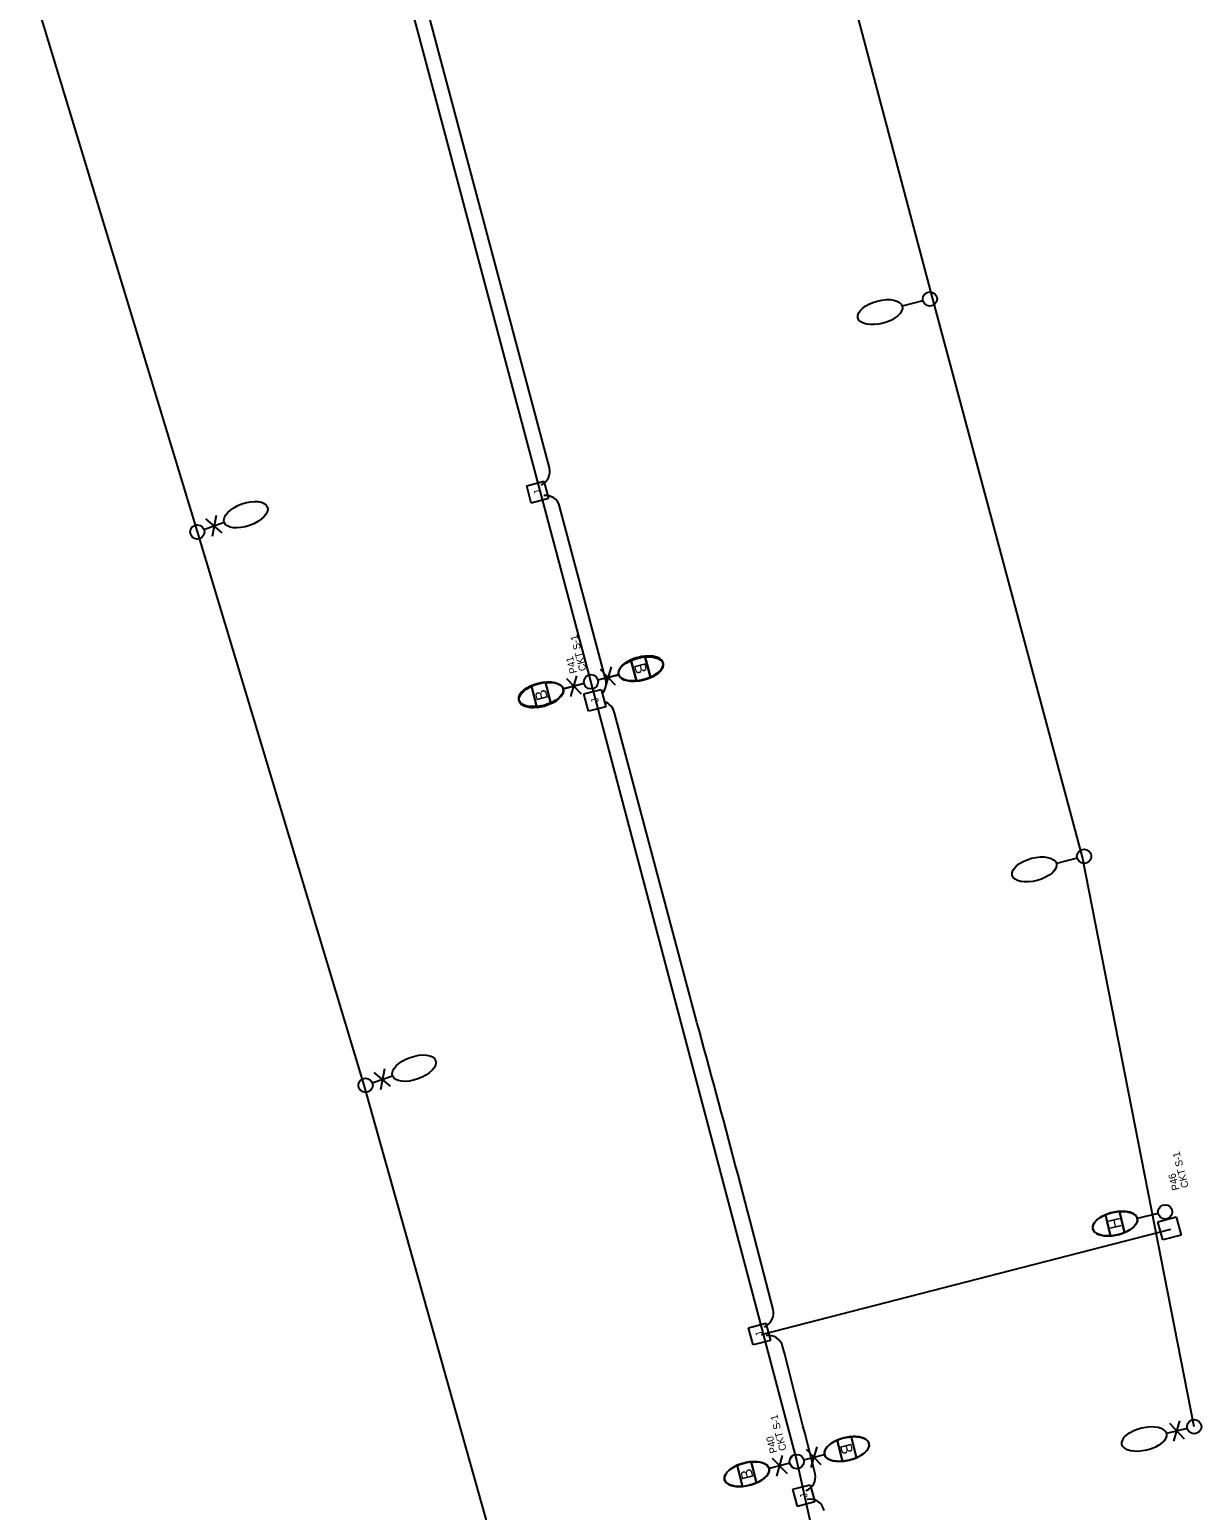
# Model space of a CAD drawing. Extents: x 925407 to 931638, y 609358 to 637063.
# Drawn here: x 930737 to 931143, y 627898 to 628410 of the extents above; entities that cross this region are included whole.
import ezdxf

# ---------------------------------------------------------------- set-up
doc = ezdxf.new("R2010")
doc.units = 0
for name, color, linetype in [('ActivePointCell_dp', 7, 'Continuous'), ('ConduitDB', 7, 'Continuous'), ('ConduitOT', 7, 'Continuous'), ('JunctBoxA', 7, 'Continuous'), ('LiteCond_ep', 7, 'Continuous'), ('Miscellaneous2', 7, 'Continuous'), ('PoleLight', 7, 'Continuous'), ('PoleLight_ep', 7, 'Continuous'), ('PullBox', 7, 'Continuous'), ('TextLabel', 7, 'Continuous')]:
    doc.layers.add(name, color=color, linetype=linetype)

msp = doc.modelspace()

# ---------------------------------------------------------------- linework, layer by layer
at = {"layer": 'ConduitDB'}
msp.add_line((931132.13, 627995.12), (930990.55, 627958.73), dxfattribs=at)
at = {"layer": 'ConduitOT'}
for p, q in [((930917.24, 628258.84), (930870.79, 628433.4)), ((930936.68, 628185.71), (930920.78, 628245.49)), ((930968.28, 628066.88), (930939.78, 628174.05))]:
    msp.add_line(p, q, dxfattribs=at)
for centre, radius, start, end in [((930912.4, 628257.55), 5, 292.8975, 14.8905), ((930915.95, 628244.21), 5, 14.8905, 97.9211), ((930931.37, 628184.3), 5.5, 319.4037, 14.8905), ((930934.47, 628172.64), 5.5, 14.8905, 70.3772), ((925389.37, 626534.36), 5785.57, 14.341695, 15.360173), ((930989.8, 627966.21), 5, 290.6915, 14.6067), ((930993.09, 627953.52), 5, 14.4768, 99.5906), ((925396.06, 626508.45), 5785.57, 14.025976, 14.476795), ((931004.28, 627909.49), 5, 290.2521, 13.4216), ((931007.43, 627896.81), 5, 13.292, 101.1054)]:
    msp.add_arc(centre, radius, start, end, dxfattribs=at)
at = {"layer": 'LiteCond_ep'}
for p, q in [((931049.63, 628318.09), (930998.15, 628512.29)), ((930859.34, 628455.99), (930931.48, 628184.94)), ((930795.39, 628237.11), (930737.39, 628428.02)), ((931101.67, 628124.08), (931049.63, 628318.09)), ((930853.17, 628045.17), (930795.39, 628237.11)), ((930931.48, 628184.94), (931002.82, 627914.87)), ((931140.34, 627926.92), (931101.67, 628124.08)), ((930906.99, 627853.38), (930853.17, 628045.17)), ((931002.82, 627914.87), (931064.34, 627640.3))]:
    msp.add_line(p, q, dxfattribs=at)
at = {"layer": 'Miscellaneous2'}
for p, q in [((930945.46, 628192.33), (930945.46, 628192.33)), ((930945.46, 628192.33), (930947.39, 628185.07)), ((930952.22, 628186.35), (930950.29, 628193.62)), ((930950.29, 628193.62), (930950.29, 628193.62)), ((930911.01, 628183.17), (930911.01, 628183.17)), ((930911.01, 628183.17), (930912.94, 628175.91)), ((930917.78, 628177.19), (930915.84, 628184.46)), ((930915.84, 628184.46), (930915.84, 628184.46)), ((931116.23, 627994.12), (931114.51, 628001.43)), ((931114.51, 628001.43), (931114.51, 628001.43)), ((931109.64, 628000.29), (931109.64, 628000.29)), ((931109.64, 628000.29), (931111.36, 627992.97)), ((931016.76, 627922.26), (931016.76, 627922.26)), ((931016.76, 627922.26), (931018.59, 627914.97)), ((931023.44, 627916.19), (931021.61, 627923.48)), ((931021.61, 627923.48), (931021.61, 627923.48)), ((930988.88, 627907.49), (930987.05, 627914.78)), ((930987.05, 627914.78), (930987.05, 627914.78)), ((930982.2, 627913.56), (930982.2, 627913.56)), ((930982.2, 627913.56), (930984.03, 627906.27))]:
    msp.add_line(p, q, dxfattribs=at)
for centre, major_axis, start_param, end_param in [((930948.84, 628189.34), (7.65, 2.04), 1.249648, 1.891946), ((930948.84, 628189.34), (7.65, 2.04), 4.391271, 5.033538), ((930914.39, 628180.18), (7.65, 2.04), 1.249648, 1.891946), ((930948.84, 628189.34), (7.65, 2.04), 4.391241, 4.391271), ((930914.39, 628180.18), (7.65, 2.04), 4.391271, 5.033538), ((930914.39, 628180.18), (7.65, 2.04), 4.391241, 4.391271), ((931112.94, 627997.2), (7.71, 1.81), 1.249648, 1.891946), ((931112.94, 627997.2), (7.71, 1.81), 4.391271, 5.033538), ((931112.94, 627997.2), (7.71, 1.81), 4.391241, 4.391271), ((931020.1, 627919.22), (7.68, 1.93), 1.249648, 1.891946), ((930985.54, 627910.52), (7.68, 1.93), 1.249648, 1.891946), ((931020.1, 627919.22), (7.68, 1.93), 4.391271, 5.033538), ((931020.1, 627919.22), (7.68, 1.93), 4.391241, 4.391271), ((930985.54, 627910.52), (7.68, 1.93), 4.391271, 5.033538), ((930985.54, 627910.52), (7.68, 1.93), 4.391241, 4.391271)]:
    msp.add_ellipse(centre, major_axis=major_axis, ratio=0.5, start_param=start_param, end_param=end_param, dxfattribs=at)
at = {"layer": 'PoleLight'}
for p, q in [((930947.39, 628185.07), (930945.46, 628192.33)), ((930950.29, 628193.62), (930952.22, 628186.35)), ((930934.01, 628185.4), (930941.18, 628187.31)), ((930912.94, 628175.91), (930911.01, 628183.17)), ((930915.84, 628184.46), (930917.78, 628177.19)), ((930929.22, 628184.13), (930922.05, 628182.22)), ((931114.51, 628001.43), (931116.23, 627994.12)), ((931111.36, 627992.97), (931109.64, 628000.29)), ((931127.87, 628000.71), (931120.64, 627999.01)), ((931018.59, 627914.97), (931016.76, 627922.26)), ((931021.61, 627923.48), (931023.44, 627916.19)), ((930987.05, 627914.78), (930988.88, 627907.49)), ((931000.42, 627914.27), (930993.22, 627912.46)), ((931005.22, 627915.48), (931012.42, 627917.29)), ((930984.03, 627906.27), (930982.2, 627913.56))]:
    msp.add_line(p, q, dxfattribs=at)
for centre, radius in [((930931.62, 628184.76), 2.48), ((930931.62, 628184.76), 2.48), ((931130.28, 628001.28), 2.48), ((931130.28, 628001.28), 2.47), ((931002.82, 627914.87), 2.48), ((931002.82, 627914.87), 2.48)]:
    msp.add_circle(centre, radius, dxfattribs=at)
for centre, major_axis in [((930948.84, 628189.34), (7.65, 2.04)), ((930914.39, 628180.18), (7.65, 2.04)), ((931112.94, 627997.2), (7.71, 1.81)), ((931020.1, 627919.22), (7.68, 1.93)), ((930985.54, 627910.52), (7.68, 1.93))]:
    msp.add_ellipse(centre, major_axis=major_axis, ratio=0.5, dxfattribs=at)
for centre, major_axis, start_param, end_param in [((930948.84, 628189.34), (7.65, 2.04), 1.891945, 4.391241), ((930948.84, 628189.34), (7.65, 2.04), 0.847605, 1.249648), ((930948.84, 628189.34), (7.65, 2.04), 5.033538, 6.283185), ((930948.84, 628189.34), (7.65, 2.04), 0, 0.847605), ((930914.39, 628180.18), (7.65, 2.04), 1.891945, 4.391241), ((930914.39, 628180.18), (7.65, 2.04), 0.847605, 1.249648), ((930914.39, 628180.18), (7.65, 2.04), 5.033538, 6.283185), ((930914.39, 628180.18), (7.65, 2.04), 0, 0.847605), ((931112.94, 627997.2), (7.71, 1.81), 0.847605, 1.249648), ((931112.94, 627997.2), (7.71, 1.81), 0, 0.847605), ((931112.94, 627997.2), (7.71, 1.81), 1.891945, 4.391241), ((931112.94, 627997.2), (7.71, 1.81), 5.033538, 6.283185), ((931020.1, 627919.22), (7.68, 1.93), 1.891945, 4.391241), ((931020.1, 627919.22), (7.68, 1.93), 0.847605, 1.249648), ((931020.1, 627919.22), (7.68, 1.93), 5.033538, 6.283185), ((931020.1, 627919.22), (7.68, 1.93), 0, 0.847605), ((930985.54, 627910.52), (7.68, 1.93), 0.847605, 1.249648), ((930985.54, 627910.52), (7.68, 1.93), 0, 0.847605), ((930985.54, 627910.52), (7.68, 1.93), 1.891945, 4.391241), ((930985.54, 627910.52), (7.68, 1.93), 5.033538, 6.283185)]:
    msp.add_ellipse(centre, major_axis=major_axis, ratio=0.5, start_param=start_param, end_param=end_param, dxfattribs=at)
at = {"layer": 'PoleLight_ep'}
for p, q in [((931046.49, 628316.61), (931039.31, 628314.72)), ((930801.89, 628242.34), (930800.55, 628235.03)), ((930797.72, 628237.44), (930804.72, 628239.93)), ((930804.04, 628236.28), (930798.39, 628241.09)), ((930923.11, 628185.9), (930928.28, 628180.57)), ((930924.68, 628179.67), (930926.71, 628186.81)), ((930934.02, 628185.37), (930941.22, 628187.17)), ((930940.12, 628183.62), (930934.95, 628188.96)), ((930938.55, 628189.86), (930936.52, 628182.72)), ((930929.21, 628184.16), (930922.01, 628182.35)), ((931099.86, 628123.72), (931092.68, 628121.83)), ((930855.95, 628045.89), (930862.95, 628048.38)), ((930862.28, 628044.73), (930856.63, 628049.54)), ((930860.12, 628050.79), (930858.78, 628043.48)), ((931137.94, 627926.33), (931130.73, 627924.56)), ((931131.76, 627928.12), (931136.9, 627922.76)), ((931133.3, 627921.88), (931135.37, 627929.01)), ((931011.31, 627913.72), (931006.15, 627919.06)), ((931009.75, 627919.96), (931007.71, 627912.82)), ((931000.41, 627914.26), (930993.21, 627912.45)), ((930994.31, 627916), (930999.47, 627910.67)), ((930995.87, 627909.77), (930997.91, 627916.91)), ((931005.21, 627915.46), (931012.41, 627917.27))]:
    msp.add_line(p, q, dxfattribs=at)
for centre, radius in [((931048.88, 628317.25), 2.47), ((930795.39, 628236.61), 2.47), ((930931.62, 628184.76), 2.48), ((931102.25, 628124.36), 2.47), ((930853.62, 628045.06), 2.47), ((931140.34, 627926.92), 2.47), ((931002.81, 627914.86), 2.48)]:
    msp.add_circle(centre, radius, dxfattribs=at)
for centre, major_axis in [((931031.65, 628312.7), (-7.66, -2.02)), ((930812.18, 628242.58), (7.46, 2.65)), ((930948.9, 628189.1), (7.68, 1.93)), ((930914.33, 628180.43), (-7.68, -1.93)), ((931085.02, 628119.81), (-7.66, -2.02)), ((930870.41, 628051.03), (7.46, 2.65)), ((931020.1, 627919.2), (7.68, 1.93)), ((931123.04, 627922.67), (-7.69, -1.89)), ((930985.53, 627910.53), (-7.68, -1.93))]:
    msp.add_ellipse(centre, major_axis=major_axis, ratio=0.5, dxfattribs=at)
at = {"layer": 'PullBox'}
for p, q in [((930909.37, 628252.59), (930915.36, 628254.18)), ((930910.97, 628246.6), (930909.37, 628252.59)), ((930915.36, 628254.18), (930916.95, 628248.19)), ((930916.95, 628248.19), (930910.97, 628246.6)), ((930929.18, 628180.52), (930935.17, 628182.11)), ((930930.78, 628174.54), (930929.18, 628180.52)), ((930935.17, 628182.11), (930936.76, 628176.13)), ((930936.76, 628176.13), (930930.78, 628174.54)), ((931127.76, 627997.88), (931134.09, 627999.57)), ((931129.44, 627991.55), (931127.76, 627997.88)), ((931134.09, 627999.57), (931135.77, 627993.24)), ((931135.77, 627993.24), (931129.44, 627991.55)), ((930986.11, 627961.19), (930992.09, 627962.78)), ((930987.7, 627955.21), (930986.11, 627961.19)), ((930992.09, 627962.78), (930993.68, 627956.8)), ((930993.68, 627956.8), (930987.7, 627955.21)), ((931001.46, 627905.27), (931007.45, 627906.86)), ((931003.05, 627899.28), (931001.46, 627905.27)), ((931007.45, 627906.86), (931009.04, 627900.87)), ((931009.04, 627900.87), (931003.05, 627899.28))]:
    msp.add_line(p, q, dxfattribs=at)

# ---------------------------------------------------------------- texts
at = {"layer": 'ActivePointCell_dp'}
for s, p in [('CKT S-1', (930930.08, 628188.83)), ('P41', (930926.84, 628187.97)), ('CKT S-1', (931138.48, 628009.94)), ('P46', (931135.24, 628009.08)), ('CKT S-1', (930999.31, 627918.96)), ('P40', (930996.07, 627918.11))]:
    msp.add_text(s, height=2.5, rotation=104.7826, dxfattribs=at).set_placement(p)
at = {"layer": 'JunctBoxA'}
for p in [(930914.58, 628249.9), (930934.39, 628177.83), (930991.31, 627958.5), (931006.66, 627902.57)]:
    msp.add_text('J', height=2.48, rotation=104.8905, dxfattribs=at).set_placement(p)
at = {"layer": 'TextLabel'}
for s, rotation, p in [('B', 284.894, (930946.43, 628190.6)), ('B', 104.894, (930916.8, 628178.93)), ('H', 103.227, (931115.3, 627995.88)), ('B', 284.1271, (931017.72, 627920.51)), ('B', 104.1271, (930987.92, 627909.24))]:
    msp.add_text(s, height=4, rotation=rotation, dxfattribs=at).set_placement(p)

doc.saveas('drawing.dxf')
